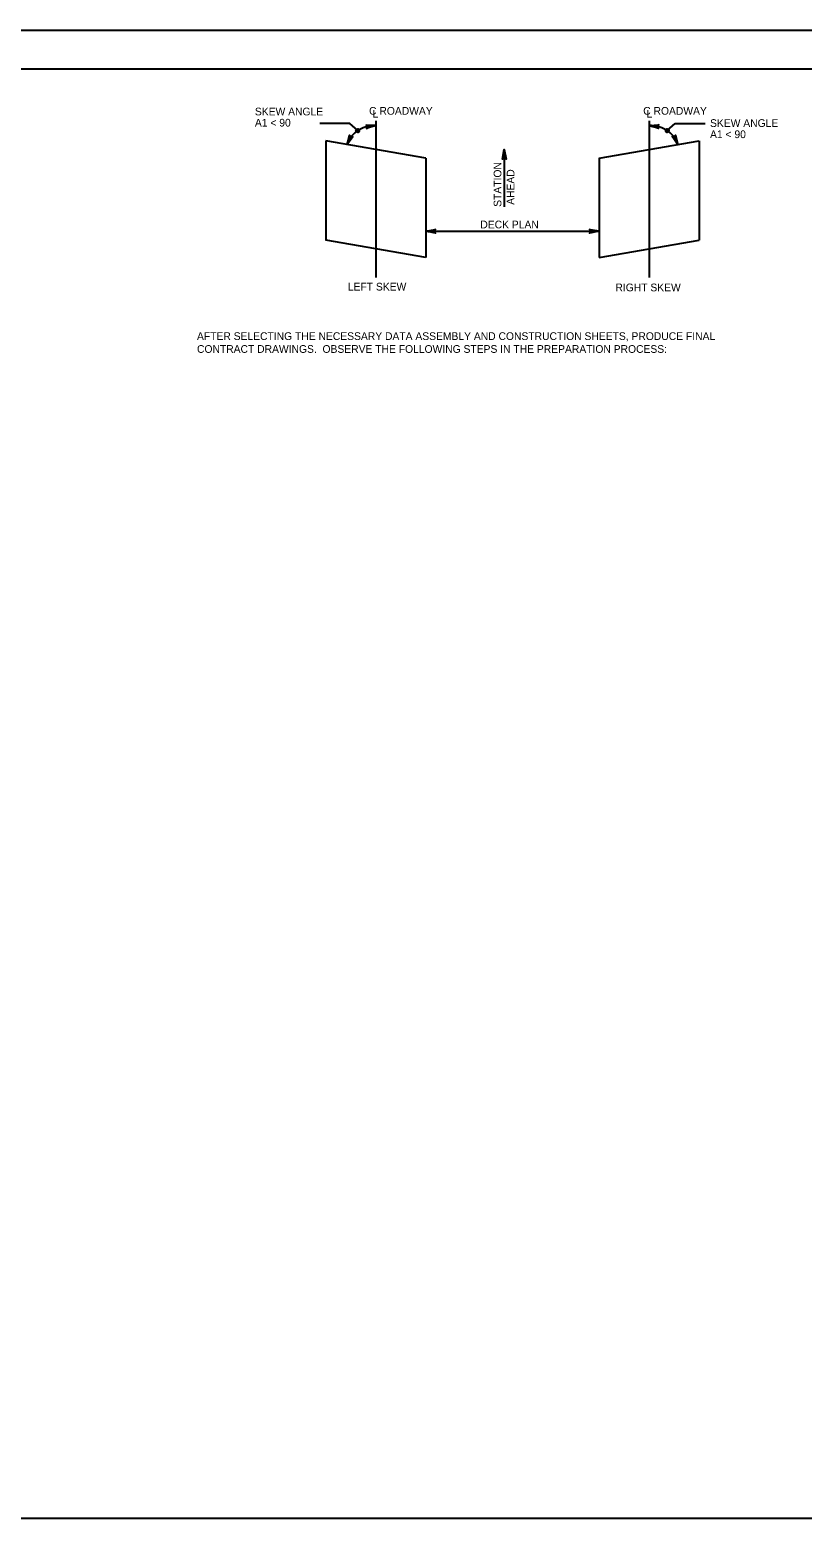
# Model space of a CAD drawing. Extents: x 637594 to 640253, y 297247 to 298527.
# Drawn here: x 639578 to 639879, y 297849 to 298435 of the extents above; entities that cross this region are included whole.
import ezdxf

# ---------------------------------------------------------------- set-up
doc = ezdxf.new("R2010")
doc.units = 0
doc.layers.add('2', color=7, linetype='Continuous')
doc.layers.add('PLT-BNDY', color=7, linetype='Continuous')

msp = doc.modelspace()

# ---------------------------------------------------------------- linework, layer by layer
at = {"layer": '2'}
for p, q in [((639316.46, 298420.46), (640102.46, 298420.46)), ((639712.61, 298400.19), (639712.61, 298339.24)), ((639818.89, 298400.19), (639818.89, 298339.24)), ((639702.44, 298399.19), (639690.83, 298399.19)), ((639705.56, 298396.37), (639702.44, 298399.19)), ((639825.94, 298396.37), (639829.06, 298399.19)), ((639829.06, 298399.19), (639840.67, 298399.19)), ((639693.16, 298392.35), (639693.16, 298353.79)), ((639732.06, 298385.64), (639693.16, 298392.35)), ((639762.53, 298389.05), (639762.53, 298366.73)), ((639799.44, 298385.64), (639838.34, 298392.35)), ((639838.34, 298392.35), (639838.34, 298353.79)), ((639732.06, 298385.64), (639732.06, 298347.08)), ((639799.44, 298385.64), (639799.44, 298347.08)), ((639732.06, 298347.08), (639693.16, 298353.79)), ((639732.06, 298357.23), (639799.44, 298357.23)), ((639799.44, 298347.08), (639838.34, 298353.79)), ((640102.46, 297856.46), (639316.46, 297856.46))]:
    msp.add_line(p, q, dxfattribs=at)
for points in [[(639701.47, 298390.91), (639702.37, 298394.6), (639702.43, 298394.25), (639702.6, 298394.02), (639702.81, 298393.88), (639703.05, 298393.81), (639703.34, 298393.84), (639703.64, 298394.02), (639701.47, 298390.91), (639703.34, 298393.84), (639703.05, 298393.81), (639701.47, 298390.91), (639702.81, 298393.88), (639702.6, 298394.02), (639701.47, 298390.91), (639702.43, 298394.25)], [(639712.61, 298398.39), (639709.03, 298397.14), (639709.28, 298397.38), (639709.39, 298397.65), (639709.4, 298397.9), (639709.32, 298398.14), (639709.14, 298398.37), (639708.82, 298398.52), (639712.61, 298398.39), (639709.14, 298398.37), (639709.32, 298398.14), (639712.61, 298398.39), (639709.4, 298397.9), (639709.39, 298397.65), (639712.61, 298398.39), (639709.28, 298397.38)], [(639818.89, 298398.39), (639822.68, 298398.61), (639822.36, 298398.45), (639822.19, 298398.22), (639822.11, 298397.98), (639822.12, 298397.73), (639822.24, 298397.46), (639822.5, 298397.23), (639818.89, 298398.39), (639822.24, 298397.46), (639822.12, 298397.73), (639818.89, 298398.39), (639822.11, 298397.98), (639822.19, 298398.22), (639818.89, 298398.39), (639822.36, 298398.45)], [(639830.03, 298390.91), (639827.89, 298394.04), (639828.18, 298393.86), (639828.47, 298393.83), (639828.72, 298393.89), (639828.93, 298394.03), (639829.1, 298394.26), (639829.16, 298394.61), (639830.03, 298390.91), (639829.1, 298394.26), (639828.93, 298394.03), (639830.03, 298390.91), (639828.72, 298393.89), (639828.47, 298393.83), (639830.03, 298390.91), (639828.18, 298393.86)], [(639762.53, 298389.05), (639763.23, 298385.32), (639763.03, 298385.61), (639762.78, 298385.75), (639762.53, 298385.8), (639762.28, 298385.75), (639762.03, 298385.61), (639761.83, 298385.32), (639762.53, 298389.05), (639762.03, 298385.61), (639762.28, 298385.75), (639762.53, 298389.05), (639762.53, 298385.8), (639762.78, 298385.75), (639762.53, 298389.05), (639763.03, 298385.61)], [(639732.06, 298357.23), (639735.79, 298357.93), (639735.5, 298357.73), (639735.35, 298357.48), (639735.31, 298357.23), (639735.35, 298356.98), (639735.5, 298356.73), (639735.79, 298356.53), (639732.06, 298357.23), (639735.5, 298356.73), (639735.35, 298356.98), (639732.06, 298357.23), (639735.31, 298357.23), (639735.35, 298357.48), (639732.06, 298357.23), (639735.5, 298357.73)], [(639799.44, 298357.23), (639795.71, 298356.53), (639796, 298356.73), (639796.15, 298356.98), (639796.19, 298357.23), (639796.15, 298357.48), (639796, 298357.73), (639795.71, 298357.93), (639799.44, 298357.23), (639796, 298357.73), (639796.15, 298357.48), (639799.44, 298357.23), (639796.19, 298357.23), (639796.15, 298356.98), (639799.44, 298357.23), (639796, 298356.73)]]:
    msp.add_lwpolyline(points, dxfattribs=at)
for centre, radius in [((639705.56, 298396.37), 0.667), ((639705.56, 298396.37), 0.333), ((639825.94, 298396.37), 0.667), ((639825.94, 298396.37), 0.333)]:
    msp.add_circle(centre, radius, dxfattribs=at)
for centre, start_param, end_param in [((639712.61, 298388.99), 2.175748, 2.935639), ((639712.61, 298388.99), 1.570796, 2.175748), ((639818.89, 298388.99), 0.965845, 1.570796), ((639818.89, 298388.99), 0.205954, 0.965845)]:
    msp.add_ellipse(centre, major_axis=(11.38, 0), ratio=0.825336, start_param=start_param, end_param=end_param, dxfattribs=at)
at = {"layer": 'PLT-BNDY'}
msp.add_lwpolyline([(639276.46, 298435.46), (640117.46, 298435.46), (640117.46, 297841.46), (639276.46, 297841.46)], close=True, dxfattribs=at)

# ---------------------------------------------------------------- texts
at = {"layer": '2'}
for s, height, p in [('SKEW ANGLE', 3, (639665.58, 298402.3)), ('C ROADWAY', 3, (639709.98, 298402.56)), ('C ROADWAY', 3, (639816.59, 298402.56)), ('A1 < 90', 3, (639665.58, 298397.95)), ('L', 3, (639711.3, 298401.43)), ('L', 3, (639817.91, 298401.43)), ('SKEW ANGLE', 3, (639842.58, 298397.81)), ('A1 < 90', 3, (639842.58, 298393.46)), ('DECK PLAN', 3, (639753.24, 298358.35)), ('LEFT SKEW', 3, (639701.72, 298334.17)), ('RIGHT SKEW', 3, (639805.78, 298333.87)), ('AFTER SELECTING THE NECESSARY DATA ASSEMBLY AND CONSTRUCTION SHEETS, PRODUCE FINAL ', 3.0001, (639643.06, 298314.93)), ('CONTRACT DRAWINGS.  OBSERVE THE FOLLOWING STEPS IN THE PREPARATION PROCESS: ', 3.0001, (639643.06, 298309.93))]:
    msp.add_text(s, height=height, dxfattribs=at).set_placement(p)
for s, p in [('STATION', (639761.43, 298366.74)), ('AHEAD', (639766.5, 298367.51))]:
    msp.add_text(s, height=3, rotation=90, dxfattribs=at).set_placement(p)

doc.saveas('drawing.dxf')
